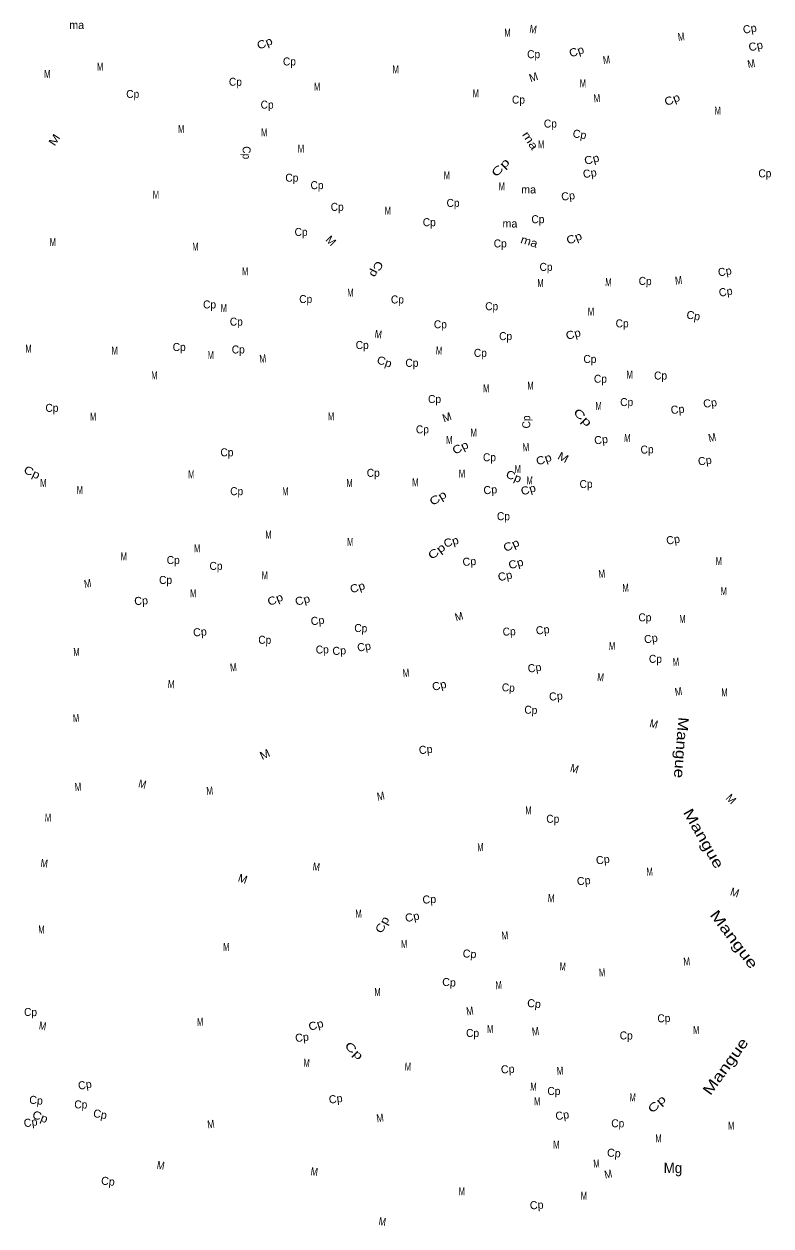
# Model space of a CAD drawing. Extents: x 713577 to 726626, y 7177731 to 7191794.
# Drawn here: x 722803 to 726350, y 7180632 to 7186338 of the extents above; entities that cross this region are included whole.
import ezdxf
from ezdxf.enums import TextEntityAlignment as Align

# ---------------------------------------------------------------- set-up
doc = ezdxf.new("R2010")
doc.units = 0
doc.header["$LTSCALE"] = 15
doc.layers.add('19', color=7, linetype='Continuous')

msp = doc.modelspace()

# ---------------------------------------------------------------- texts
at = {"layer": '19'}
for s, rotation, p in [('ma', 359.988, (723053.33, 7186314.25)), ('Cp', 10.678, (726252.47, 7186296.74)), ('Cp', 350.528, (725438.41, 7185795.52)), ('Cp', 9.134, (725492.33, 7185610.79)), ('ma', 359.988, (725199.11, 7185533.41)), ('Cp', 7.125, (725388.82, 7185502.61)), ('ma', 359.988, (725110.3, 7185371.87)), ('M', 315, (724246.91, 7185295.59)), ('Cp', 10.222, (726133.78, 7185144.57)), ('Cp', 9.866, (726137.82, 7185048.27)), ('Cp', 350.275, (725978.35, 7184935.07)), ('Cp', 8.17, (726063.35, 7184519.89)), ('M', 19.183, (724817.32, 7184453.46)), ('Cp', 6.428, (725908.4, 7184489.35)), ('Cp', 7.636, (725545.42, 7184345.59)), ('Cp', 8.17, (726038.15, 7184246.19)), ('Cp', 5.607, (725018.99, 7184107.59)), ('Cp', 10.037, (725888.07, 7183871.17)), ('Cp', 4.863, (724919.3, 7183767.26)), ('Cp', 4.13, (723360.58, 7183581.11)), ('Cp', 6.657, (724198.97, 7183486.9)), ('Cp', 5.784, (723640.28, 7183432.72)), ('Cp', 7.313, (725268.27, 7183442.66)), ('Cp', 10.188, (724420.91, 7183363.38)), ('Cp', 9.196, (725782.36, 7183401.75)), ('Cp', 3.564, (724301.18, 7183343.83)), ('Cp', 9.219, (725230.05, 7183262.98)), ('Cp', 5.787, (725330.47, 7183128.03)), ('Cp', 6.142, (724712.47, 7182874.64)), ('M', 313.958, (726147.07, 7182645.61)), ('Cp', 7.768, (725553.75, 7182351.94)), ('M', 341.527, (723835.89, 7182262.04)), ('Cp', 5.845, (725462.65, 7182251.83)), ('Cp', 3.566, (724728.78, 7182163.47)), ('Cp', 355.691, (724917.43, 7181904.98)), ('Cp', 356.124, (724820.18, 7181770.03)), ('Cp', 353.683, (725223.02, 7181668.95)), ('Cp', 6.641, (724125.24, 7181508.31)), ('Cp', 3.793, (725101.17, 7181357.51)), ('Cp', 9.749, (723095.21, 7181283.43)), ('Cp', 354.22, (722858.78, 7181210.15)), ('Cp', 8.671, (724285.75, 7181216.67)), ('Cp', 349.037, (723161.15, 7181143.99)), ('Cp', 9.73, (725361.77, 7181138.86)), ('Cp', 9.371, (722837.47, 7181105.1)), ('Cp', 354.798, (725602.45, 7180959.41)), ('Cp', 353.71, (723199.98, 7180825.51)), ('Cp', 3.905, (725238.69, 7180712.37))]:
    msp.add_text(s, height=38, rotation=rotation, dxfattribs=at).set_placement(p, align=Align.CENTER)
for s, height, rotation, width, p in [('M', 38, 359.988, 0.65, (725098.94, 7186277.42)), ('M', 38, 350.743, 0.8, (725217.75, 7186294.35)), ('Cp', 38, 22.041, 1.15, (723952.94, 7186229.52)), ('M', 38, 6.908, 0.75, (725925.97, 7186258.44)), ('Cp', 38, 359.988, 0.95, (725223.02, 7186175.41)), ('Cp', 38, 18.54, 1.1, (725432.5, 7186190.21)), ('Cp', 38, 12.628, 1.05, (726281.38, 7186214.96)), ('M', 38, 359.988, 0.65, (723164.64, 7186116.01)), ('Cp', 38, 359.988, 0.95, (724063.52, 7186140.98)), ('M', 38, 359.988, 0.65, (724567.86, 7186103.16)), ('M', 38, 7.433, 0.8, (725571.32, 7186149.02)), ('M', 38, 10.991, 0.85, (726260.03, 7186130.81)), ('M', 38, 359.988, 0.65, (722913.98, 7186081.72)), ('Cp', 38, 359.343, 0.95, (723806.87, 7186044.6)), ('M', 38, 18.435, 0.95, (725228.14, 7186067.69)), ('Cp', 38, 359.988, 0.95, (723319.5, 7185986.52)), ('M', 38, 359.988, 0.65, (724194.99, 7186021.34)), ('M', 38, 359.988, 0.65, (724948.28, 7185989.47)), ('M', 38, 1.228, 0.7, (725457.36, 7186037.64)), ('Cp', 38, 359.988, 0.95, (723957.46, 7185935.92)), ('Cp', 38, 359.988, 0.95, (725150.98, 7185959.77)), ('M', 38, 4.899, 0.75, (725525.5, 7185966.89)), ('Cp', 38, 22.109, 1.15, (725887.42, 7185961.86)), ('M', 38, 1.885, 0.7, (726097.87, 7185907.69)), ('M', 38, 359.988, 0.65, (723549.65, 7185820.69)), ('Cp', 38, 359.988, 0.95, (725302.54, 7185846.13)), ('M', 38, 56.31, 1.25, (722963.15, 7185777.4)), ('M', 38, 359.988, 0.65, (723943.96, 7185803.76)), ('ma', 38, 302.521, 1.3, (725190.96, 7185774.38)), ('Cp', 38, 270, 0.95, (723841.31, 7185726.74)), ('M', 38, 359.988, 0.65, (724118.31, 7185726.44)), ('M', 38, 359.988, 0.65, (725258.66, 7185747.33)), ('Cp', 38, 46.331, 1.5, (725079.09, 7185643.59)), ('Cp', 38, 15.078, 1.1, (725503.59, 7185677.51)), ('Cp', 38, 359.988, 0.95, (724074.96, 7185589.14)), ('M', 38, 359.988, 0.65, (724811.15, 7185601.13)), ('Cp', 38, 0.611, 0.95, (726321, 7185609.89)), ('Cp', 38, 359.988, 0.95, (724194.5, 7185553.77)), ('M', 38, 359.988, 0.65, (725071.7, 7185548.24)), ('M', 38, 359.988, 0.65, (723429.7, 7185508.96)), ('Cp', 38, 359.988, 0.95, (724290.25, 7185450.72)), ('M', 38, 359.988, 0.65, (724530.73, 7185432.43)), ('Cp', 38, 359.988, 0.95, (724840.44, 7185469.42)), ('Cp', 38, 359.988, 0.95, (724727.48, 7185377.97)), ('Cp', 38, 359.988, 0.95, (725243.33, 7185392.06)), ('Cp', 38, 359.988, 0.95, (724118.82, 7185331.53)), ('Cp', 38, 22.001, 1.15, (725422.14, 7185303.74)), ('M', 38, 359.988, 0.65, (722939.9, 7185283.18)), ('M', 38, 359.988, 0.65, (723616.9, 7185261.56)), ('Cp', 38, 359.988, 0.95, (725064.31, 7185277.17)), ('ma', 38, 342.537, 1.15, (725196.8, 7185287.38)), ('M', 38, 359.988, 0.65, (723853, 7185144.94)), ('Cp', 38, 243.435, 1.2, (724459.82, 7185182.03)), ('Cp', 38, 359.988, 0.95, (725281.92, 7185165.83)), ('M', 38, 359.988, 0.65, (725255.22, 7185089.15)), ('M', 38, 358.548, 0.7, (725577.4, 7185093.28)), ('Cp', 38, 357.781, 0.95, (725751.78, 7185098.89)), ('M', 38, 7.397, 0.8, (725913.44, 7185102.46)), ('M', 38, 359.988, 0.65, (724352.97, 7185042.78)), ('Cp', 38, 359.988, 0.95, (723684.14, 7184987.51)), ('M', 38, 359.988, 0.65, (723751.91, 7184970.59)), ('Cp', 38, 359.988, 0.95, (724140.88, 7185013.17)), ('Cp', 38, 359.988, 0.95, (724576.15, 7185011.1)), ('Cp', 38, 359.988, 0.95, (725023.96, 7184978.97)), ('Cp', 38, 359.988, 0.95, (723811.27, 7184905.91)), ('M', 38, 359.988, 0.65, (725495.28, 7184953.7)), ('M', 38, 351.48, 0.8, (724482.81, 7184846.42)), ('Cp', 38, 359.988, 0.95, (724780.21, 7184893.15)), ('Cp', 38, 15.39, 1.1, (725416.1, 7184847.53)), ('Cp', 38, 359.988, 0.95, (725643.15, 7184897.59)), ('Cp', 38, 359.988, 0.95, (724409, 7184794.82)), ('Cp', 38, 359.988, 0.95, (725089.97, 7184837.27)), ('M', 38, 359.988, 0.65, (722824.53, 7184777.59)), ('M', 38, 359.988, 0.65, (723233.71, 7184768.59)), ('Cp', 38, 359.988, 0.95, (723540.11, 7184785.43)), ('M', 38, 359.988, 0.65, (723689.77, 7184747.02)), ('Cp', 38, 359.988, 0.95, (723820.49, 7184773.81)), ('M', 38, 7.054, 0.75, (723939.66, 7184730.78)), ('M', 38, 355.99, 0.7, (724772.31, 7184768.45)), ('Cp', 38, 359.988, 0.95, (724970.08, 7184757.71)), ('Cp', 38, 341.546, 1.1, (724508.81, 7184716.86)), ('Cp', 38, 359.988, 0.95, (724645.1, 7184710.23)), ('Cp', 38, 359.988, 0.95, (725490.21, 7184728.54)), ('M', 38, 359.988, 0.65, (723422.25, 7184651.31)), ('Cp', 38, 359.988, 0.95, (725540.06, 7184634.74)), ('M', 38, 359.988, 0.65, (725678.83, 7184654.46)), ('Cp', 38, 359.988, 0.95, (725825.73, 7184649.87)), ('M', 38, 359.988, 0.65, (724997.85, 7184589.54)), ('M', 38, 359.988, 0.65, (725207.89, 7184602.38)), ('Cp', 38, 359.988, 0.95, (724752.73, 7184538.47)), ('M', 38, 359.988, 0.65, (725531.51, 7184505.55)), ('Cp', 38, 359.988, 0.95, (725664.87, 7184524.08)), ('Cp', 38, 359.988, 0.95, (722935.96, 7184496.46)), ('M', 38, 359.988, 0.65, (723131.26, 7184454.54)), ('M', 38, 0.442, 0.65, (724261.44, 7184456.92)), ('Cp', 38, 315, 1.5, (725442.59, 7184457.14)), ('Cp', 38, 359.988, 0.95, (724694.9, 7184394.5)), ('Cp', 38, 90, 0.95, (725206.96, 7184448.73)), ('M', 38, 359.988, 0.65, (724822.76, 7184343.88)), ('M', 38, 359.988, 0.65, (724938.36, 7184378.53)), ('M', 38, 356.332, 0.7, (725666.25, 7184353.47)), ('M', 38, 11.976, 0.85, (726074.53, 7184356.62)), ('Cp', 38, 359.988, 0.95, (723766.82, 7184285.58)), ('Cp', 38, 27.012, 1.2, (724883.53, 7184310.44)), ('M', 38, 4.394, 0.75, (725188.55, 7184310)), ('Cp', 38, 2.227, 0.95, (725762.23, 7184299.02)), ('Cp', 38, 359.988, 0.95, (725013.23, 7184262)), ('Cp', 38, 19.276, 1.15, (725277.17, 7184253.82)), ('M', 38, 331.905, 1.15, (725354.55, 7184263.89)), ('Cp', 38, 334.634, 1.2, (722833.18, 7184192.29)), ('M', 38, 359.988, 0.65, (723597.51, 7184181)), ('Cp', 38, 359.988, 0.95, (724461.37, 7184188.14)), ('M', 38, 359.988, 0.65, (724882.83, 7184184.68)), ('Cp', 38, 337.06, 1.15, (725121.64, 7184172.84)), ('M', 38, 1.325, 0.7, (725148.24, 7184206.36)), ('M', 38, 359.988, 0.65, (722895.07, 7184140.2)), ('M', 38, 359.988, 0.65, (723068.44, 7184106.81)), ('M', 38, 359.988, 0.65, (724349.15, 7184139.89)), ('M', 38, 359.988, 0.65, (724661.23, 7184142.79)), ('Cp', 38, 17.432, 1.1, (725203.13, 7184109.83)), ('M', 38, 359.085, 0.7, (725203.65, 7184152.18)), ('Cp', 38, 2.086, 0.95, (725472.64, 7184135.33)), ('Cp', 38, 359.988, 0.95, (723813.01, 7184100.97)), ('M', 38, 359.988, 0.65, (724044.32, 7184100.65)), ('Cp', 38, 32.641, 1.3, (724779.06, 7184072.15)), ('Cp', 38, 359.307, 0.95, (725079.47, 7183982.25)), ('M', 38, 359.988, 0.65, (723963.69, 7183894.6)), ('M', 38, 359.988, 0.65, (723625.51, 7183829.61)), ('M', 38, 359.988, 0.65, (724352.39, 7183860.5)), ('Cp', 38, 37.396, 1.35, (724773.91, 7183819.69)), ('Cp', 38, 16.444, 1.1, (724836.6, 7183862.08)), ('Cp', 38, 24.51, 1.2, (725124.46, 7183846.77)), ('M', 38, 359.988, 0.65, (723277.09, 7183791.05)), ('Cp', 38, 359.988, 0.95, (723511.76, 7183774.09)), ('M', 38, 359.988, 0.65, (726102.2, 7183768.91)), ('Cp', 38, 359.988, 0.95, (723714.85, 7183746.3)), ('Cp', 38, 15.776, 1.1, (725143.92, 7183758.51)), ('M', 38, 6.543, 0.75, (725549.39, 7183708.87)), ('M', 38, 10.002, 0.8, (723108.75, 7183663.28)), ('Cp', 38, 359.988, 0.95, (723475.41, 7183679.64)), ('M', 38, 359.988, 0.65, (723946.48, 7183701.4)), ('Cp', 38, 11.494, 1.05, (725090.82, 7183699.29)), ('M', 38, 359.988, 0.65, (723606.64, 7183616.6)), ('Cp', 38, 23.171, 1.15, (724003.1, 7183589.06)), ('Cp', 38, 18.142, 1.1, (724392.22, 7183645.78)), ('M', 38, 2.813, 0.7, (725660.58, 7183642.54)), ('M', 38, 358.915, 0.7, (726125.17, 7183626.48)), ('Cp', 38, 14.475, 1.1, (724130.17, 7183585.01)), ('M', 38, 15.383, 0.9, (724873.6, 7183506.78)), ('Cp', 38, 359.977, 0.95, (725751.39, 7183502.1)), ('Cp', 38, 357.19, 0.95, (724401.43, 7183450.8)), ('Cp', 38, 2.39, 0.95, (725107.45, 7183434.88)), ('Cp', 38, 358.275, 0.95, (723945.98, 7183395.34)), ('M', 38, 358.277, 0.7, (725594.85, 7183366.11)), ('M', 38, 2.49, 0.7, (723053.2, 7183337.76)), ('Cp', 38, 1.148, 0.95, (724219.77, 7183349.43)), ('M', 38, 6.266, 0.75, (723799.44, 7183265.36)), ('M', 38, 3.994, 0.7, (725900.13, 7183291.14)), ('M', 38, 6.385, 0.75, (724619.52, 7183238.33)), ('M', 38, 354.318, 0.75, (725539.2, 7183218.41)), ('M', 38, 355.912, 0.75, (723500.56, 7183185.05)), ('Cp', 38, 14.26, 1.05, (724779.17, 7183179.75)), ('Cp', 38, 356.889, 0.95, (725101.89, 7183168.93)), ('M', 38, 9.987, 0.8, (725913.9, 7183150.54)), ('M', 38, 3.807, 0.7, (723051.81, 7183023.67)), ('Cp', 38, 356.935, 0.95, (725208.85, 7183062.82)), ('M', 38, 345.941, 0.9, (725789.08, 7182996.7)), ('Mangue', 50, 265.796, 1.2, (725899.58, 7182904.16)), ('M', 38, 25.009, 1.1, (723954.79, 7182853.64)), ('M', 38, 343.629, 0.9, (725411.87, 7182785.11)), ('M', 38, 5.175, 0.75, (723061.96, 7182697.28)), ('M', 38, 346.69, 0.85, (723361.07, 7182710.87)), ('M', 38, 4.712, 0.75, (723686.53, 7182679.08)), ('M', 38, 11.071, 0.85, (724500.66, 7182653.94)), ('M', 38, 0.743, 0.65, (725198.77, 7182586.21)), ('Mangue', 50, 299.752, 1.3, (726008.62, 7182458.97)), ('M', 38, 359.437, 0.65, (722917.16, 7182551.09)), ('Cp', 38, 359.551, 0.95, (725313.81, 7182545.74)), ('M', 38, 1.177, 0.7, (724970.65, 7182411.04)), ('M', 38, 352.398, 0.8, (722897.12, 7182335.09)), ('M', 38, 352.504, 0.8, (724188.93, 7182318.03)), ('M', 38, 1.982, 0.7, (725774.46, 7182295.04)), ('M', 38, 355.666, 0.75, (725304.89, 7182168.64)), ('M', 38, 341.879, 0.95, (726172.37, 7182197.25)), ('M', 38, 3.005, 0.7, (724393.05, 7182095.4)), ('Cp', 38, 62.216, 1.25, (724520.75, 7182053.22)), ('Cp', 38, 12.794, 1.05, (724650.44, 7182080.87)), ('Mangue', 50, 306.969, 1.35, (726155.06, 7181977.85)), ('M', 38, 359.008, 0.7, (722885.55, 7182020.28)), ('M', 38, 6.451, 0.75, (725089.36, 7181992.28)), ('M', 38, 357.856, 0.7, (723762.54, 7181937.25)), ('M', 38, 2.363, 0.7, (724609.12, 7181951.79)), ('M', 38, 356.65, 0.7, (725359.85, 7181845.12)), ('M', 38, 5.448, 0.75, (725951.68, 7181868.77)), ('M', 38, 3.387, 0.7, (725549.23, 7181816.35)), ('M', 38, 0.495, 0.65, (724481.84, 7181724.01)), ('M', 38, 3.598, 0.7, (725058.38, 7181756.49)), ('Cp', 38, 358.498, 0.95, (722833.86, 7181628.58)), ('M', 38, 8.601, 0.8, (724923.06, 7181633.52)), ('Cp', 38, 2.017, 0.95, (725841.89, 7181599.24)), ('M', 38, 350.928, 0.8, (722888.9, 7181563.14)), ('M', 38, 0.715, 0.65, (723639.78, 7181581.86)), ('Cp', 38, 16.845, 1.1, (724194.75, 7181568.11)), ('M', 38, 359.988, 0.65, (725016.8, 7181547.95)), ('M', 38, 8.008, 0.8, (725234.43, 7181536.89)), ('M', 38, 359.988, 0.65, (725994.94, 7181543.66)), ('Cp', 38, 359.638, 0.95, (724933.06, 7181528.95)), ('Cp', 38, 358.861, 0.95, (725662.22, 7181517.15)), ('Mangue', 50, 54.196, 1.3, (726154.05, 7181375.48)), ('Cp', 38, 315.649, 1.5, (724356.98, 7181450.51)), ('M', 38, 356.575, 0.7, (724144.11, 7181387.04)), ('M', 38, 357.238, 0.7, (724625.04, 7181369.43)), ('M', 38, 4.958, 0.75, (725350.36, 7181349.8)), ('M', 38, 357.022, 0.7, (725221.16, 7181274.26)), ('Cp', 38, 359.988, 0.95, (725319.22, 7181253.63)), ('M', 38, 359.988, 0.65, (725240.05, 7181205.07)), ('M', 38, 357.909, 0.7, (725692.39, 7181223.25)), ('Cp', 38, 42.924, 1.45, (725820.65, 7181196.87)), ('Cp', 38, 338.573, 1.15, (722873.37, 7181132.87)), ('Cp', 38, 358.896, 0.95, (723072.6, 7181189.75)), ('M', 38, 8.211, 0.8, (723693.21, 7181096.55)), ('M', 38, 8.274, 0.8, (724496.56, 7181126.29)), ('Cp', 38, 359.334, 0.95, (725622.29, 7181100.27)), ('M', 38, 359.988, 0.65, (726160.88, 7181088.74)), ('M', 38, 359.988, 0.65, (725815.75, 7181028.65)), ('M', 38, 359.988, 0.65, (725330.85, 7180999.08)), ('M', 38, 3.517, 0.7, (725522.42, 7180908.93)), ('M', 38, 349.333, 0.85, (723449.17, 7180901.21)), ('M', 38, 352.248, 0.8, (724179.34, 7180871.14)), ('M', 38, 11.678, 0.85, (725580.81, 7180859.89)), ('M', 38, 359.988, 0.65, (724882.15, 7180777.77)), ('M', 38, 359.988, 0.65, (725461.45, 7180756.01)), ('M', 38, 350.947, 0.8, (724501.94, 7180634.08))]:
    msp.add_text(s, height=height, rotation=rotation, dxfattribs=dict(at, width=width)).set_placement(p, align=Align.CENTER)
for s, height, width, p in [('M', 38, 0.65, (725929.3, 7183494.5)), ('Cp', 38, 0.95, (725801.2, 7183305.15)), ('M', 38, 0.65, (726128.9, 7183145.78)), ('Mg', 50, 0.95, (725884.45, 7180882.64))]:
    msp.add_text(s, height=height, dxfattribs=dict(at, width=width)).set_placement(p, align=Align.CENTER)

doc.saveas('drawing.dxf')
